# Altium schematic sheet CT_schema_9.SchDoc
size 146 x 119 mm
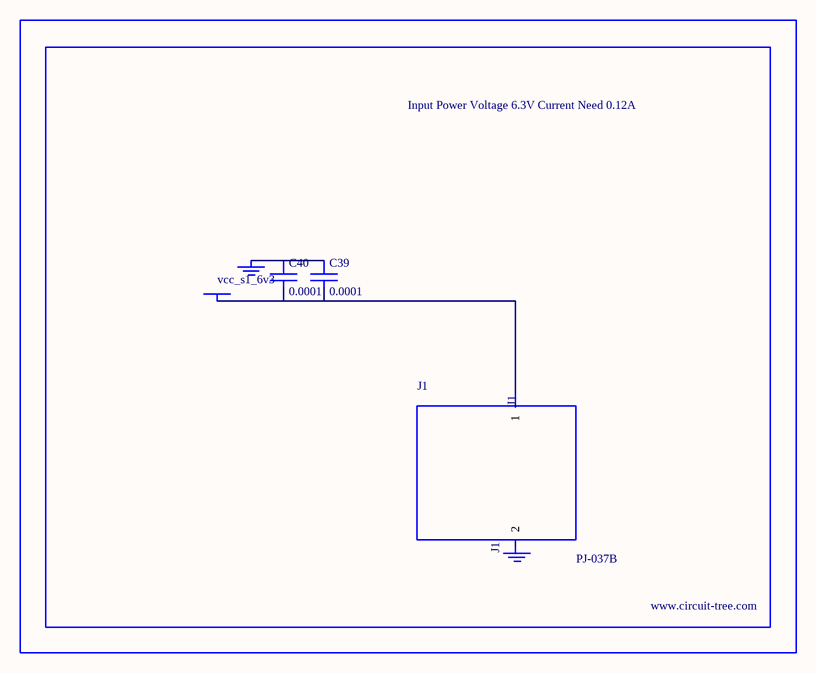
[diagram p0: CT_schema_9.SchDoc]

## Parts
BORDER8  (no value)
C39  0.0001  [EXV-9H]
C40  0.0001  [EXV-9H]
GND_INSTANCE_8_0  (no value)
GND_INSTANCE_8_1  (no value)
J1  PJ-037B  [PJ-037B_PACKAGE]
POWER_INSTANCE_8_0  vcc_s1_6v3

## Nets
NetC39_1: C39.1 C40.1 GND_INSTANCE_8_0.0(GND)
NetC39_2: C39.2 C40.2 J1.1 POWER_INSTANCE_8_0.0(PWR)

Not connected (* = marked no-connect by the designer): GND_INSTANCE_8_1 0(GND); J1 2

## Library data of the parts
BORDER8 = BORDER_PAGE8
C39 C40 = EDK107M035A9HAA
GND_INSTANCE_8_0 GND_INSTANCE_8_1 = GND
POWER_INSTANCE_8_0 = PWR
